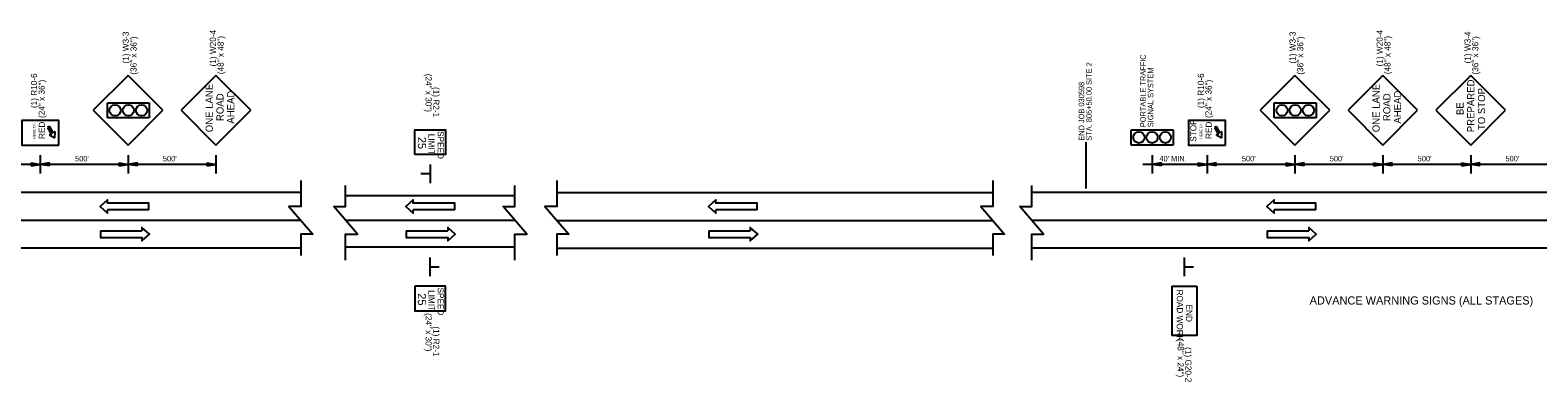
# Model space of a CAD drawing. Extents: x 1368648 to 1927880, y -1037443 to 380209.
# Drawn here: x 1370245 to 1371716, y 377732 to 378075 of the extents above; entities that cross this region are included whole.
import ezdxf

# ---------------------------------------------------------------- set-up
doc = ezdxf.new("R2010")
doc.units = 0
for name, color, linetype in [('Default', 7, 'Continuous'), ('Dimensions', 7, 'Continuous'), ('R_Draft', 7, 'Continuous'), ('R_Signs', 7, 'Continuous'), ('R_Signs_Annot', 7, 'Continuous')]:
    doc.layers.add(name, color=color, linetype=linetype)

# ---------------------------------------------------------------- blocks, each defined once
blk = doc.blocks.new('ARROW')
at = {"layer": 'R_Draft'}
for p, q in [((-2, 0.3), (0, 0)), ((-2, 0.3), (-2, -0.3)), ((-2, 0.25), (-0.334, 0)), ((-2, 0.199), (-0.678, 0)), ((-2, 0.149), (-1.011, 0)), ((-2, 0.097), (-1.35, 0)), ((-2, 0.047), (-1.684, 0)), ((-2, -0.3), (0, 0)), ((-2, -0.098), (-1.35, 0)), ((-2, -0.199), (-0.678, 0)), ((-2, -0.25), (-0.334, 0)), ((-2, -0.149), (-1.011, 0)), ((-2, -0.047), (-1.684, 0))]:
    blk.add_line(p, q, dxfattribs=at)

msp = doc.modelspace()

# ---------------------------------------------------------------- linework, layer by layer
at = {"layer": 'Default'}
for p, q in [((1371275.7, 377920.6), (1371275.7, 377965.7)), ((1370255.2, 377944.1), (1370201.5, 377944.1)), ((1370255.2, 377944.1), (1370246.1, 377944.1)), ((1370255.2, 377953.2), (1370255.2, 377935.1)), ((1370340.9, 377944.1), (1370255.2, 377944.1)), ((1370340.9, 377944.1), (1370331.9, 377944.1)), ((1370340.9, 377953.2), (1370340.9, 377935.1)), ((1370426.6, 377944.1), (1370340.9, 377944.1)), ((1370426.6, 377944.1), (1370417.6, 377944.1)), ((1370426.6, 377953.2), (1370426.6, 377935.1)), ((1370635.5, 377944), (1370635.5, 377925.9)), ((1371340.1, 377944.1), (1371331.1, 377944.1)), ((1371340.1, 377953.2), (1371340.1, 377935.1)), ((1371393.7, 377944.1), (1371340.1, 377944.1)), ((1371393.7, 377944.1), (1371384.7, 377944.1)), ((1371393.7, 377953.2), (1371393.7, 377935.1)), ((1371479.5, 377944.1), (1371393.7, 377944.1)), ((1371479.5, 377944.1), (1371470.5, 377944.1)), ((1371479.5, 377953.2), (1371479.5, 377935.1)), ((1371565.2, 377944.1), (1371479.5, 377944.1)), ((1371565.2, 377944.1), (1371556.2, 377944.1)), ((1371565.2, 377953.2), (1371565.2, 377935.1)), ((1371651, 377944.1), (1371565.2, 377944.1)), ((1371651, 377944.1), (1371641.9, 377944.1)), ((1371651, 377944.1), (1371641.9, 377944.1)), ((1371651, 377953.2), (1371651, 377935.1)), ((1371651, 377953.2), (1371651, 377935.1)), ((1371736.7, 377944.1), (1371651, 377944.1)), ((1370635.5, 377934.9), (1370626.4, 377934.9)), ((1370509.4, 377916.5), (1370084, 377916.5)), ((1370718.3, 377913.3), (1370553.1, 377913.3)), ((1370759.2, 377916.5), (1371184.6, 377916.5)), ((1371928, 377916.5), (1371222.6, 377916.5)), ((1370509.4, 377889.4), (1370084, 377889.4)), ((1370718.3, 377889.4), (1370553.1, 377889.4)), ((1370759.2, 377889.4), (1371184.6, 377889.4)), ((1371928, 377889.4), (1371222.6, 377889.4)), ((1370509.4, 377862.4), (1370084, 377862.4)), ((1370718.3, 377863.2), (1370553.1, 377863.2)), ((1370635.5, 377834.9), (1370635.5, 377853)), ((1370759.2, 377862.4), (1371184.6, 377862.4)), ((1371928, 377862.4), (1371222.6, 377862.4)), ((1371371.4, 377853), (1371371.4, 377834.9)), ((1370635.5, 377843.9), (1370644.5, 377843.9)), ((1371371.4, 377843.9), (1371380.4, 377843.9))]:
    msp.add_line(p, q, dxfattribs=at)
for points in [[(1370509.4, 377928.4), (1370509.4, 377903), (1370497.8, 377903), (1370521, 377875.9), (1370509.4, 377875.9), (1370509.4, 377855.2)], [(1370759.2, 377928.4), (1370759.2, 377903), (1370747.6, 377903), (1370770.8, 377875.9), (1370759.2, 377875.9), (1370759.2, 377855.2)], [(1371184.6, 377928.4), (1371184.6, 377903), (1371173, 377903), (1371196.2, 377875.9), (1371184.6, 377875.9), (1371184.6, 377855.2)], [(1370553.1, 377850.5), (1370553.1, 377875.9), (1370564.7, 377875.9), (1370541.5, 377903), (1370553.1, 377903), (1370553.1, 377923.6)], [(1370718.3, 377850.5), (1370718.3, 377875.9), (1370729.8, 377875.9), (1370706.7, 377903), (1370718.3, 377903), (1370718.3, 377923.6)], [(1371222.6, 377850.5), (1371222.6, 377875.9), (1371234.2, 377875.9), (1371211, 377903), (1371222.6, 377903), (1371222.6, 377923.6)]]:
    msp.add_lwpolyline(points, dxfattribs=at)
at = {"layer": 'Dimensions'}
for p, q in [((1370361.2, 377899.7), (1370320.6, 377899.7)), ((1370659.6, 377899.7), (1370619, 377899.7)), ((1370954.8, 377899.7), (1370914.2, 377899.7)), ((1371499.8, 377899.7), (1371459.2, 377899.7)), ((1370313.9, 377879.1), (1370354.4, 377879.1)), ((1370612.2, 377879.1), (1370652.8, 377879.1)), ((1370907.4, 377879.1), (1370948, 377879.1)), ((1371452.4, 377879.1), (1371493, 377879.1))]:
    msp.add_line(p, q, dxfattribs=at)
for points in [[(1370361.2, 377899.7), (1370361.2, 377906.2), (1370320.6, 377906.2), (1370320.6, 377909.5), (1370313.5, 377903), (1370320.6, 377896.5), (1370320.6, 377899.7)], [(1370659.6, 377899.7), (1370659.6, 377906.2), (1370619, 377906.2), (1370619, 377909.5), (1370611.9, 377903), (1370619, 377896.5), (1370619, 377899.7)], [(1370954.8, 377899.7), (1370954.8, 377906.2), (1370914.2, 377906.2), (1370914.2, 377909.5), (1370907.1, 377903), (1370914.2, 377896.5), (1370914.2, 377899.7)], [(1371499.8, 377899.7), (1371499.8, 377906.2), (1371459.2, 377906.2), (1371459.2, 377909.5), (1371452.1, 377903), (1371459.2, 377896.5), (1371459.2, 377899.7)], [(1370313.9, 377879.1), (1370313.9, 377872.6), (1370354.4, 377872.6), (1370354.4, 377869.4), (1370361.6, 377875.9), (1370354.4, 377882.4), (1370354.4, 377879.1)], [(1370612.2, 377879.1), (1370612.2, 377872.6), (1370652.8, 377872.6), (1370652.8, 377869.4), (1370659.9, 377875.9), (1370652.8, 377882.4), (1370652.8, 377879.1)], [(1370907.4, 377879.1), (1370907.4, 377872.6), (1370948, 377872.6), (1370948, 377869.4), (1370955.2, 377875.9), (1370948, 377882.4), (1370948, 377879.1)], [(1371452.4, 377879.1), (1371452.4, 377872.6), (1371493, 377872.6), (1371493, 377869.4), (1371500.2, 377875.9), (1371493, 377882.4), (1371493, 377879.1)]]:
    msp.add_lwpolyline(points, dxfattribs=at)
at = {"layer": 'R_Signs'}
for p, q in [((1370340.9, 378030.9), (1370306.9, 377997)), ((1370374.8, 377997), (1370340.9, 378030.9)), ((1370426.6, 378030.9), (1370392.7, 377997)), ((1370460.6, 377997), (1370426.6, 378030.9)), ((1371479.5, 378030.9), (1371445.5, 377997)), ((1371513.4, 377997), (1371479.5, 378030.9)), ((1371565.2, 378030.9), (1371531.3, 377997)), ((1371599.2, 377997), (1371565.2, 378030.9)), ((1371651, 378030.9), (1371617, 377997)), ((1371684.9, 377997), (1371651, 378030.9)), ((1370320.8, 377989.5), (1370320.8, 378004.3)), ((1370320.8, 378004.3), (1370361.4, 378004.3)), ((1370361.4, 378004.3), (1370361.4, 377989.5)), ((1371459.3, 377989.5), (1371459.3, 378004.3)), ((1371459.3, 378004.3), (1371500, 378004.3)), ((1371500, 378004.3), (1371500, 377989.5)), ((1370306.9, 377997), (1370340.9, 377963)), ((1370361.4, 377989.5), (1370320.8, 377989.5)), ((1370340.9, 377963), (1370374.8, 377997)), ((1370392.7, 377997), (1370426.6, 377963)), ((1370426.6, 377963), (1370460.6, 377997)), ((1371445.5, 377997), (1371479.5, 377963)), ((1371500, 377989.5), (1371459.3, 377989.5)), ((1371479.5, 377963), (1371513.4, 377997)), ((1371531.3, 377997), (1371565.2, 377963)), ((1371565.2, 377963), (1371599.2, 377997)), ((1371617, 377997), (1371651, 377963)), ((1371651, 377963), (1371684.9, 377997)), ((1370264.2, 377981.1), (1370262.3, 377980)), ((1370262.3, 377980), (1370266.1, 377973.6)), ((1370268, 377974.7), (1370264.2, 377981.1)), ((1370264.6, 377972.5), (1370264.6, 377972.5)), ((1370264.6, 377972.5), (1370269.4, 377970)), ((1370266.1, 377973.6), (1370264.7, 377973.3)), ((1370264.7, 377973.3), (1370264.7, 377973.3)), ((1370268.9, 377975.7), (1370268, 377974.7)), ((1370268.9, 377975.7), (1370268.9, 377975.7)), ((1370269.4, 377970), (1370269.6, 377975.4)), ((1370269.6, 377975.4), (1370269.6, 377975.4)), ((1371319.8, 377963), (1371319.8, 377977.9)), ((1371319.8, 377977.9), (1371360.5, 377977.9)), ((1371360.5, 377977.9), (1371360.5, 377963)), ((1371402.8, 377981.1), (1371400.9, 377980)), ((1371400.9, 377980), (1371404.7, 377973.6)), ((1371406.6, 377974.7), (1371402.8, 377981.1)), ((1371403.2, 377972.5), (1371403.2, 377972.5)), ((1371403.2, 377972.5), (1371408, 377970)), ((1371404.7, 377973.6), (1371403.3, 377973.3)), ((1371403.3, 377973.3), (1371403.3, 377973.3)), ((1371407.5, 377975.7), (1371406.6, 377974.7)), ((1371407.5, 377975.7), (1371407.5, 377975.7)), ((1371408, 377970), (1371408.2, 377975.4)), ((1371408.2, 377975.4), (1371408.2, 377975.4)), ((1371360.5, 377963), (1371319.8, 377963))]:
    msp.add_line(p, q, dxfattribs=at)
for points in [[(1370273.2, 377963), (1370273.2, 377987), (1370237.2, 377987), (1370237.2, 377963)], [(1371411.7, 377963), (1371411.7, 377987), (1371375.7, 377987), (1371375.7, 377963)], [(1370620.5, 377953.8), (1370620.5, 377977.8), (1370650.5, 377977.8), (1370650.5, 377953.8)], [(1370620.5, 377825), (1370620.5, 377801), (1370650.5, 377801), (1370650.5, 377825)], [(1371383.7, 377825), (1371383.7, 377777), (1371359.7, 377777), (1371359.7, 377825)]]:
    msp.add_lwpolyline(points, close=True, dxfattribs=at)
for centre in [(1370328.2, 377996.9), (1370341.1, 377996.9), (1370341.1, 377996.9), (1370354, 377996.9), (1371466.8, 377996.9), (1371479.7, 377996.9), (1371479.7, 377996.9), (1371492.6, 377996.9), (1371327.2, 377970.4), (1371340.1, 377970.4), (1371340.1, 377970.4), (1371353, 377970.4)]:
    msp.add_circle(centre, 5.48, dxfattribs=at)
for centre, start, end in [((1370264.8, 377972.9), 103.0563, 242.5967), ((1370269.2, 377975.4), 357.4033, 136.9437), ((1371403.4, 377972.9), 103.0563, 242.5967), ((1371407.8, 377975.4), 357.4033, 136.9437)]:
    msp.add_arc(centre, 0.41, start, end, dxfattribs=at)

# ---------------------------------------------------------------- block references
at = {"layer": 'Default', "xscale": 4.512500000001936, "yscale": 4.512499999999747}
for p in [(1370255.2, 377944.1), (1370340.9, 377944.1), (1370340.9, 377944.1), (1370426.6, 377944.1), (1370426.6, 377944.1), (1371393.7, 377944.1), (1371479.5, 377944.1), (1371479.5, 377944.1), (1371565.2, 377944.1), (1371565.2, 377944.1), (1371651, 377944.1)]:
    msp.add_blockref('ARROW', p, dxfattribs=at)
at = {"layer": 'Default', "xscale": 4.512500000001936, "yscale": 4.512499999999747, "rotation": 180}
for p in [(1370255.2, 377944.1), (1370255.2, 377944.1), (1370340.9, 377944.1), (1370340.9, 377944.1), (1371340.1, 377944.1), (1371393.7, 377944.1), (1371393.7, 377944.1), (1371479.5, 377944.1), (1371479.5, 377944.1), (1371565.2, 377944.1), (1371651, 377944.1)]:
    msp.add_blockref('ARROW', p, dxfattribs=at)

# ---------------------------------------------------------------- texts
at = {"layer": 'Default'}
for s, height, rotation, p in [('STA. 805+50.00 SITE 2', 5.415, 90, (1371281.2, 377967.2)), ('PORTABLE TRAFFIC ', 5.415, 90, (1371333.9, 377980.4)), ('SIGNAL SYSTEM', 5.415, 90, (1371341.3, 377980.4)), ('END JOB 030598', 5.415, 90, (1371273.8, 377967.2)), ("500'", 5.41, 360, (1370289.1, 377947)), ("500'", 5.41, 360, (1370374.8, 377947)), ("40' MIN.", 5.41, 360, (1371347.2, 377947)), ("500'", 5.41, 360, (1371427.7, 377947)), ("500'", 5.41, 360, (1371513.4, 377947)), ("500'", 5.41, 360, (1371599.2, 377947)), ("500'", 5.41, 360, (1371684.9, 377947))]:
    msp.add_text(s, height=height, rotation=rotation, dxfattribs=at).set_placement(p)
msp.add_text('ADVANCE WARNING SIGNS (ALL STAGES)', height=8, dxfattribs=at).set_placement((1371493.8, 377807.2))
at = {"layer": 'R_Signs'}
for s, height, rotation, p in [('ONE LANE', 7, 90, (1370423.5, 377975.5)), ('ROAD', 7, 90, (1370434, 377986.4)), ('AHEAD', 7, 90, (1370444.5, 377983.9)), ('ONE LANE', 7, 90, (1371562.1, 377975.5)), ('ROAD', 7, 90, (1371572.6, 377986.4)), ('AHEAD', 7, 90, (1371583.1, 377983.9)), ('PREPARED', 7, 90, (1371654.5, 377975.5)), ('TO STOP', 7, 90, (1371665, 377977.6)), ('BE', 7, 90, (1371644, 377992.3)), ('HERE ON', 2.5, 90, (1370250.5, 377968.9)), ('RED', 6, 90, (1370259.7, 377968.9)), ('STOP', 6, 90, (1371383.3, 377966.2)), ('HERE ON', 2.5, 90, (1371389.1, 377968.9)), ('RED', 6, 90, (1371398.3, 377968.9)), ('25', 8, 270, (1370623.6, 377971)), ('LIMIT', 6, 270, (1370633.9, 377974)), ('SPEED', 6, 270, (1370642.9, 377976.6)), ('SPEED', 6, 270, (1370642.9, 377823.8)), ('ROAD WORK', 6, 270, (1371364.2, 377821.8)), ('25', 8, 270, (1370623.6, 377818.2)), ('LIMIT', 6, 270, (1370633.9, 377821.3)), ('END', 6, 270, (1371373.2, 377807.1))]:
    msp.add_text(s, height=height, rotation=rotation, dxfattribs=at).set_placement(p)
at = {"layer": 'R_Signs_Annot'}
for s, rotation, p in [('(1) W3-3', 90, (1370341.5, 378042.6)), ('(1) W20-4', 90, (1370426.6, 378039.8)), ('(1) W3-3', 90, (1371480.1, 378042.6)), ('(1) W20-4', 90, (1371565.1, 378039.8)), ('(1) W3-4', 90, (1371650.9, 378042.7)), ('(36" x 36")', 90, (1370349.1, 378031.7)), ('(48" x 48")', 90, (1370434.1, 378032.2)), ('(36" x 36")', 90, (1371487.6, 378031.7)), ('(48" x 48")', 90, (1371572.7, 378032.2)), ('(36" x 36")', 90, (1371658.4, 378031.9)), ('(1) R10-6', 90, (1370252, 377999.1)), ('(24" x 30")', 270, (1370631.1, 378032.6)), ('(1) R10-6', 90, (1371390.6, 377999.1)), ('(24" x 36")', 90, (1370259.5, 377989.4)), ('(1) R2-1', 270, (1370638.6, 378019.7)), ('(24" x 36")', 90, (1371398.1, 377989.4)), ('(24" x 30")', 270, (1370631.1, 377798.8)), ('(1) R2-1', 270, (1370638.6, 377785.9)), ('(48" x 24")', 270, (1371365, 377773.6)), ('(1) G20-2', 270, (1371372.5, 377765.6))]:
    msp.add_text(s, height=6, rotation=rotation, dxfattribs=at).set_placement(p)

doc.saveas('drawing.dxf')
